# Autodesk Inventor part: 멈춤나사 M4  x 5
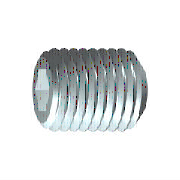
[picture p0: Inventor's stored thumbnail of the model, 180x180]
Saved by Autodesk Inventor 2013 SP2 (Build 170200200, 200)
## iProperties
IsCustomPart: 1
Created: 2012-02
Part Number: 멈춤나사 M4  x 5
Material: 강철, 연강
Description: 6각 소켓 머리 없는 멈춤 나사
Document SubType Name: Modeling
Standard: KS B 1028
Designer: mduedu
Standards Organization: KS
Language: ko-KR
Size Designation: 납작점M4x5
Categories: <MemberInstance><Categories><Category DisplayName="조임쇠" InternalName="e4da775c-781d-43d5-af7c-5136215cf5a6" Mnemonic="FSTN"><Category DisplayName="볼트" InternalN
Density: 1 g/cm^3
Author: mduedu
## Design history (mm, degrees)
sketch "스케치1"
  geometry: L1 (0, 0)-(4.833, 0); L2 (8, 1.155)-(8, 2); L3 (8, 2)-(0, 2); L4 (8, 1.155)-(5.5, 1.155); L5 (5.5, 1.155)-(4.833, 0); L6 (0, -0.4)-(0, 2.4) reference; L7 (0, 2)-(0, 0)
  constraints: 13 end point, 3 parallel, 1 collinear, 1 perpendicular, 1 point on line
  dimensions: "d0" = 2.5 distance of L2.start L4.end (= INTI); "d1" = 60 deg angle of L5 L1; "d2" = 4 diameter of L3 L1 (= NND); "d3" = 2.3094 diameter of L4 L1 (= 1.1547 x SW); "d5" = 8 distance from line of L2 L3.end (= NLG)
revolve "본체" sketch "스케치1" stored, may be unused: angle "d6" = 90 deg
sketch "스케치2"
  geometry: L1 (-0.577, 1)-(0.577, 1); L2 (0.577, 1)-(1.155, 0); L3 (1.155, 0)-(0.577, -1); L4 (0.577, -1)-(-0.577, -1); L5 (-0.577, -1)-(-1.155, 0); L6 (-1.155, 0)-(-0.577, 1); A1 r 1.155 centre (0, 0) between (-0.577, 1) and (0.577, 1) reference; 2 further points
  constraints: 12 end point, 2 point on circle, 1 coincident, 1 horizontal, 11 other
extrude "슬롯" join sketch "스케치2" taper "d9" = 0 deg; stored distance "d21" = 10
workaxis "Work Axis1"
workplane "Work Plane1"
body "Solid1"
chamfer "모따기1" distance "d7" = 0.42941 (= -0.5 x GD1 + 0.5 x NND); stored, may be unused: angle "d8" = 45 deg (= FAWI), second distance "d29" = 0.42941 (= -0.5 x GD1 + 0.5 x NND)
feature "스레드" dims "d11" = 8 (= NLG), "d12" = 0
chamfer "모따기2" distance "d13" = 0.42941 (= -0.5 x GD1 + 0.5 x NND); stored, may be unused: angle "d14" = 45 deg (= FAWI), second distance "d30" = 0.42941 (= -0.5 x GD1 + 0.5 x NND)
other parameters: "NND" = 4 [user parameter; used in 5 equation terms], "NLG" = 8 [user parameter; used in 2 equation terms], "INTI" = 2.5 [user parameter; used in 1 equation term], "FAWI" = 45 deg [user parameter; used in 2 equation terms], "SW" = 2 [user parameter; used in 2 equation terms], "GD1" = 3.14117 (= THREADDIA - 1.2269 x PTC) [user parameter; used in 4 equation terms], "d4" = 0, "FAWI1" = 45 deg [user parameter], "d15" = 0, "d31" = 0, "GUL" = 0.42941 (= 0.61345 x PTC) [user parameter], "SPD" = 2.5 [user parameter], "TPU" = 14.28571 (computed from PTC) [user parameter], "TOA" = 30 deg [user parameter], "THREADDIA" = 4 [user parameter; used in 1 equation term], "PTC" = 0.7 [user parameter; used in 4 equation terms], "GAL" = 0.42941 (= 0.61345 x PTC) [user parameter], "E0" = 2.31 (= 1.155 x SW) [user parameter]
